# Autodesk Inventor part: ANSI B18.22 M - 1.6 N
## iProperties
Comments: To add or edit properties for Autodesk Inventor files, use iProperties.
Created: 2004-08
Part Number: ANSI B18.22 M - 1.6 N
Vendor: Autodesk Inc.
Document SubType Name: Modeling
Designer: John Blackburn
Material: Default
Description: Plain Washer
Standard: ANSI B18.22 M
Alert: To add or edit properties for Autodesk Inventor files, use iProperties.
Control State: 0
Master: False
Checked Out: False
Shininess: 64.0
Length Units: 11269
Angle Units: 11279
Time Units: 11290
Mass Units: 11283
Length Display Precision: 3
Angle Display Precision: 2
Compacted: True
Classification: un/spsc 31161807
Density: 0.0
Volumn: 0.0
Area: 0.0
PropertySet Name: Model Information
Author: John Blackburn
Revision Number: 8
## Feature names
1. Body [Extrusion]
